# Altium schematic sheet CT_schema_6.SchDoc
size 372 x 335 mm
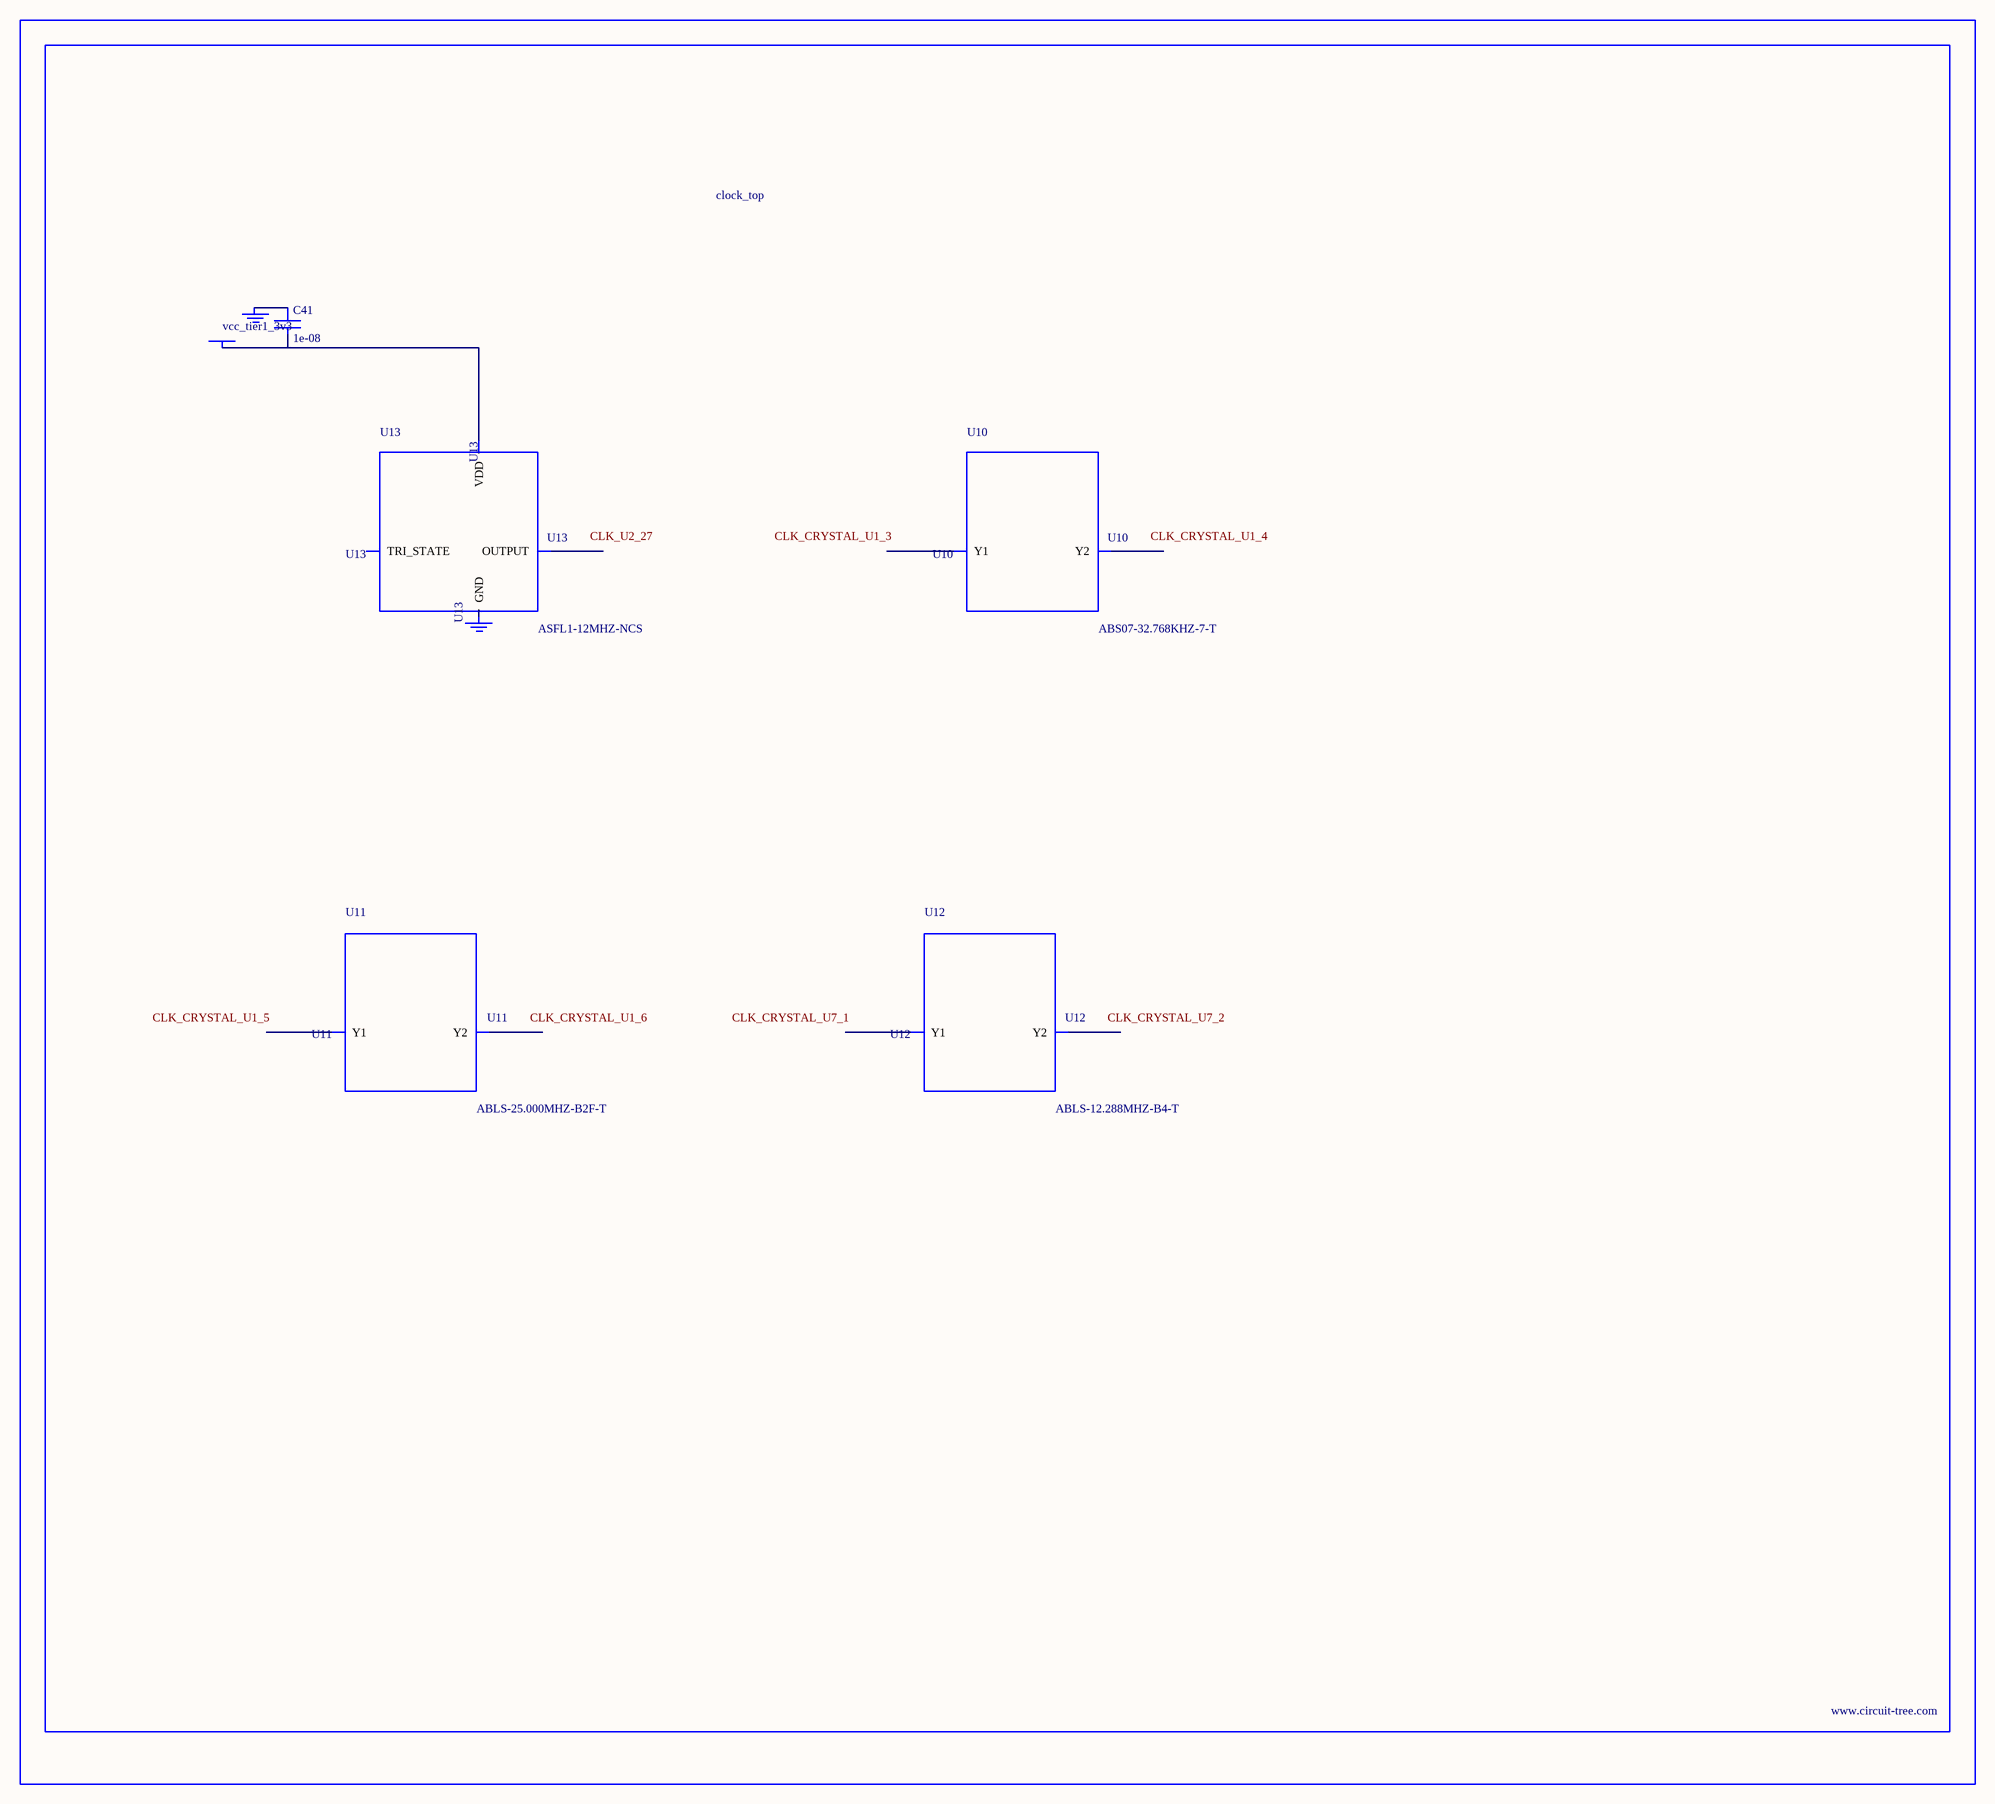
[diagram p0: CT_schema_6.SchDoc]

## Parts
BORDER5  (no value)
C41  1e-08  [C0402]
GND_INSTANCE_5_0  (no value)
GND_INSTANCE_5_1  (no value)
POWER_INSTANCE_5_0  vcc_tier1_3v3
U10  ABS07-32.768KHZ-7-T  [ABS07-32.768KHZ-7-T]
U11  ABLS-25.000MHZ-B2F-T  [ABLS-25.000MHZ-B2F-T]
U12  ABLS-12.288MHZ-B4-T  [ABLS-12.288MHZ-B4-T]
U13  ASFL1-12MHZ-NCS  [ASFL1]

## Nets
NetC41_1: C41.1 GND_INSTANCE_5_0.0(GND)
NetC41_2: C41.2 POWER_INSTANCE_5_0.0(PWR) U13.4(VDD)

Not connected (* = marked no-connect by the designer): GND_INSTANCE_5_1 0(GND); U10 1(Y1) 2(Y2); U11 1(Y1) 2(Y2); U12 1(Y1) 2(Y2); U13 1(TRI_STATE) 2(GND) 3(OUTPUT)

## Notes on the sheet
- Labels drawn without touching a wire or pin: CLK_CRYSTAL_U1_3, CLK_CRYSTAL_U1_4, CLK_CRYSTAL_U1_5, CLK_CRYSTAL_U1_6, CLK_CRYSTAL_U7_1, CLK_CRYSTAL_U7_2, CLK_U2_27

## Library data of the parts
BORDER5 = BORDER_PAGE5
C41 = C0402C103K3RAC
GND_INSTANCE_5_0 GND_INSTANCE_5_1 = GND
POWER_INSTANCE_5_0 = PWR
